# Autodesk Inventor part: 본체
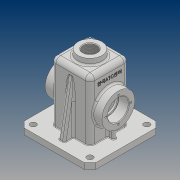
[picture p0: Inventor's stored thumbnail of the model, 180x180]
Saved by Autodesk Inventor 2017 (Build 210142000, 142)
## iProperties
Part Number: 본체
Material: 일반
Document SubType Name: Modeling
Designer: 20
Density: 1 g/cm^3
Appearance: 기본값
Mass: 293.223 g
Surface Area: 897.811 cm^2
Volume: 293.223 cm^3
Author: 20
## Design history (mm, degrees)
sketch "스케치1"
  geometry: L1 (-32.5, -32.5)-(32.5, -32.5); L2 (32.5, -32.5)-(32.5, 32.5); L3 (32.5, 32.5)-(-32.5, 32.5); L4 (-32.5, 32.5)-(-32.5, -32.5); L5 (-32.5, -32.5)-(32.5, 32.5); L6 (32.5, -32.5)-(-32.5, 32.5); 1 further point
  constraints: 12 end point, 2 midpoint, 2 parallel, 1 horizontal, 1 perpendicular
  dimensions: "d0" = 65 distance of L3.end L2.end; "d1" = 65 distance of L2.end L1.end
extrude "돌출1" new body sketch "스케치1" distance "d2" = 110; taper "d3" = 0 deg
sketch "스케치2"
  geometry: L1 (27.5, 27.5)-(-27.5, 27.5); L2 (-27.5, 27.5)-(-27.5, -27.5); L3 (-27.5, -27.5)-(27.5, -27.5); L4 (27.5, -27.5)-(27.5, 27.5); L5 (27.5, 27.5)-(-27.5, -27.5); L6 (-27.5, 27.5)-(27.5, -27.5); 1 further point
  constraints: 12 end point, 2 midpoint, 2 parallel, 1 horizontal, 1 perpendicular
  dimensions: "d4" = 55 distance of L3.end L2.end; "d5" = 55 distance of L2.end L1.end
extrude "돌출2" cut sketch "스케치2" distance "d6" = 105; taper "d7" = 0 deg
sketch "스케치3"
  geometry: L1 (60, -60)-(-60, -60); L2 (-60, -60)-(-60, 60); L3 (-60, 60)-(60, 60); L4 (60, 60)-(60, -60); L5 (60, -60)-(-60, 60); L6 (-60, -60)-(60, 60); L7 (27.5, -27.5)-(-27.5, -27.5) reference; L8 (-27.5, -27.5)-(-27.5, 27.5) reference; L9 (-27.5, 27.5)-(27.5, 27.5) reference; L10 (27.5, 27.5)-(27.5, -27.5) reference; 1 further point
  constraints: 12 end point, 2 midpoint, 2 parallel, 1 horizontal, 1 perpendicular
  dimensions: "d8" = 120 distance of L2.end L3.end; "d9" = 120 distance of L1.end L2.end
extrude "돌출3" join sketch "스케치3" distance "d10" = 10; taper "d11" = 0 deg
sketch "스케치4"
  geometry: C1 r 20 at (0, 0); 1 further point
  constraints: 1 centre point, 1 coincident
  dimensions: "d12" = 40 diameter of C1
extrude "돌출4" join sketch "스케치4" distance "d13" = 10; taper "d14" = 0 deg
feature "면 기울기2" dims angle "d16" = 5 deg
sketch "스케치5"
  geometry: L1 (110, -27.5)-(110, 92.5) reference; C1 r 27.5 at (55, 32.5); 2 further points
  constraints: 1 centre point, 1 horizontal alignment, 1 midpoint
  dimensions: "d17" = 55 diameter of C1; "d92" = 55 distance from line of L1 C1.centre
extrude "돌출5" join sketch "스케치5" distance "d18" = 15; taper "d19" = 0 deg
sketch "스케치6"
  geometry: C1 r 27.5 at (0, 0) reference; C2 r 17.5 at (0, 0); 1 further point
  constraints: 1 centre point, 1 coincident
  dimensions: "d20" = 35 diameter of C2
extrude "돌출6" cut sketch "스케치6" distance "d21" = 17; taper "d22" = 0 deg
sketch "스케치7"
  geometry: C1 r 17.5 at (0, 0) reference; C2 r 15 at (0, 0); 1 further point
  constraints: 1 centre point, 1 coincident
  dimensions: "d23" = 30 diameter of C2
extrude "돌출7" cut sketch "스케치7" distance "d24" = 3; taper "d25" = 0 deg
fillet "모깎기3" dims "d28" = 3
fillet "모깎기4" dims "d29" = 3
sketch "스케치8" dims "d30" = 42
  geometry: C1 r 27.5 at (0, 0) reference; 3 further points
  constraints: 2 horizontal alignment, 1 coincident, 2 other
hole "구멍1" sketch "스케치8" at (-21, 0) diameter "d31" = 3.242; stored, may be unused: countersink angle "d35" = 90 deg, drill point angle "d37" = 118 deg; dims "d32" = 8, "d33" = 4, "d34" = 2, "d36" = 10
hole "구멍2" diameter "d43" = 22.835; stored, may be unused: countersink angle "d47" = 90 deg, drill point angle "d49" = 118 deg; dims "d41" = 10, "d42" = 10, "d44" = 50, "d45" = 4, "d46" = 2, "d48" = 15
sketch "스케치9"
  geometry: L1 (-60, 10)-(60, 10) reference; L2 (-42.5, 10)-(-42.5, 25); L3 (-27.5, 0)-(-27.5, 102) reference; 1 further point
  constraints: 2 end point, 1 point on line, 1 vertical
  dimensions: "d50" = 15 distance between parallel lines of L2 L3; "d51" = 15 distance of L2.start L2.end
feature "리브1" sketch "스케치9" dims "d52" = 1, "d53" = 6, "d54" = 0, "d55" = 0, "d56" = 1, "d57" = 1
sketch "스케치10"
  geometry: L1 (48, 10)-(37.42, 70); L2 (60, 0)-(60, 10) reference; L3 (60, 10)-(-60, 10) reference; 1 further point
  constraints: 2 end point, 1 point on line
  dimensions: "d58" = 10 deg angle of L2 L1; "d59" = 12 distance from line of L2 L1.start; "d60" = 60 vertical distance of L1.start L1.end
feature "리브2" sketch "스케치10" dims "d61" = 1, "d62" = 10, "d63" = 0, "d64" = 0, "d65" = 1, "d66" = 1
node "작업 평면1"
chamfer "모따기1" distance "d72" = 10; stored, may be unused: second distance "d73" = 2, angle "d74" = 45 deg
sketch "스케치12"
  geometry: C1 r 5 at (-47.5, -47.5); 1 further point
  constraints: 1 centre point
  dimensions: "d75" = 10 diameter of C1; "d76" = 47.5 horizontal distance of point (0, 0) C1.centre; "d77" = 47.5 horizontal distance of C1.centre point (0, 0)
extrude "돌출8" cut sketch "스케치12" stored distance "d78" = 10; taper "d79" = 0 deg
chamfer "모따기2" distance "d86" = 1; stored, may be unused: second distance "d87" = 2, angle "d88" = 45 deg
fillet "모깎기5" dims "d89" = 0.3
fillet "모깎기6" dims "d90" = 3
sketch "스케치13"
  geometry: L1 (-32.5, 10)-(-32.5, 110) reference; L2 (20, 120)-(-20, 120) reference; 2 further points
  constraints: 1 other
  dimensions: "d95" = 32.5 distance from line of point (0, 94) L1; "d96" = 26 distance from line of L2 point (0, 94)
feature "엠보싱2" sketch "스케치13" dims "d8" = 120, "d9" = 120, "d97" = 0.5, "d98" = 0
fillet "모깎기10" dims "d99" = 8
fillet "모깎기11" dims "d100" = 8
fillet "모깎기12" dims "d101" = 3
fillet "모깎기13" dims "d102" = 3
fillet "모깎기14" dims "d103" = 3
fillet "모깎기15" dims "d104" = 3
fillet "모깎기16" dims "d105" = 1
node "솔리드1"
pattern_circular "원형 패턴1" dims angle "d39" = 360 deg
mirror "미러1"
mirror "미러2"
mirror "미러3"
pattern_linear "직사각형 패턴1" dims "d82" = 95, "d85" = -95
